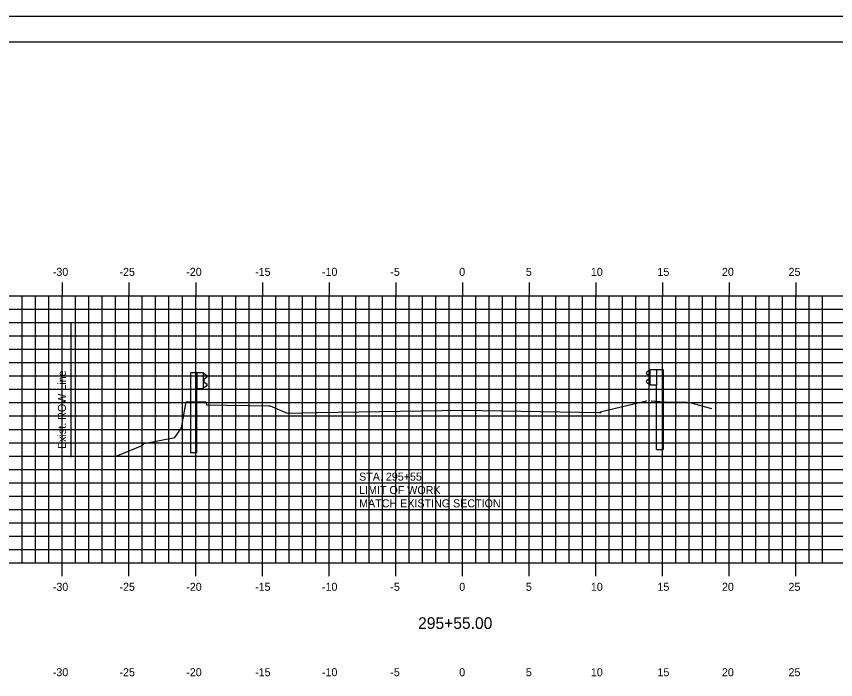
# Model space of a CAD drawing. Extents: x 859575 to 859745, y 366268 to 366378.
# Drawn here: x 859624.4 to 859685.8, y 366328.5 to 366378.2 of the extents above; entities that cross this region are included whole.
import ezdxf

# ---------------------------------------------------------------- set-up
doc = ezdxf.new("R2010")
doc.units = 0
for name, color, linetype in [('BORDER', 7, 'Continuous'), ('D_Text_Standard', 7, 'Continuous'), ('E_ROW_Line', 7, 'Continuous'), ('H_V ANNOTATION', 7, 'Continuous'), ('MAJOR', 7, 'Continuous'), ('MINOR', 7, 'Continuous'), ('PLOT BOUNDARY', 7, 'Continuous'), ('S_Guardrail_Beam', 7, 'Continuous'), ('S_Roadway_Centerline', 7, 'Continuous')]:
    doc.layers.add(name, color=color, linetype=linetype)

msp = doc.modelspace()

# ---------------------------------------------------------------- linework, layer by layer
at = {"layer": 'BORDER'}
msp.add_line((859742.797, 366376.236), (859582.797, 366376.236), dxfattribs=at)
at = {"layer": 'E_ROW_Line'}
msp.add_line((859628.47, 366345.162), (859628.47, 366355.162), dxfattribs=at)
at = {"layer": 'MAJOR'}
for p, q in [((859627.797, 366358.238), (859627.797, 366357.236)), ((859632.797, 366358.238), (859632.797, 366357.236)), ((859637.797, 366358.238), (859637.797, 366357.236)), ((859642.797, 366358.238), (859642.797, 366357.236)), ((859647.797, 366358.238), (859647.797, 366357.236)), ((859652.797, 366358.238), (859652.797, 366357.236)), ((859657.797, 366358.238), (859657.797, 366357.236)), ((859662.797, 366358.238), (859662.797, 366357.236)), ((859667.797, 366358.238), (859667.797, 366357.236)), ((859672.797, 366358.238), (859672.797, 366357.236)), ((859677.797, 366358.238), (859677.797, 366357.236)), ((859682.797, 366358.238), (859682.797, 366357.236)), ((859587.797, 366357.236), (859727.797, 366357.236)), ((859587.797, 366357.236), (859727.797, 366357.236)), ((859587.797, 366357.236), (859727.797, 366357.236)), ((859627.797, 366337.236), (859627.797, 366357.236)), ((859627.797, 366337.236), (859627.797, 366357.236)), ((859632.797, 366337.236), (859632.797, 366357.236)), ((859632.797, 366337.236), (859632.797, 366357.236)), ((859637.797, 366337.236), (859637.797, 366357.236)), ((859637.797, 366337.236), (859637.797, 366357.236)), ((859642.797, 366337.236), (859642.797, 366357.236)), ((859642.797, 366337.236), (859642.797, 366357.236)), ((859647.797, 366337.236), (859647.797, 366357.236)), ((859647.797, 366337.236), (859647.797, 366357.236)), ((859652.797, 366337.236), (859652.797, 366357.236)), ((859652.797, 366337.236), (859652.797, 366357.236)), ((859657.797, 366337.236), (859657.797, 366357.236)), ((859657.797, 366337.236), (859657.797, 366357.236)), ((859662.797, 366337.236), (859662.797, 366357.236)), ((859662.797, 366337.236), (859662.797, 366357.236)), ((859667.797, 366337.236), (859667.797, 366357.236)), ((859667.797, 366337.236), (859667.797, 366357.236)), ((859672.797, 366337.236), (859672.797, 366357.236)), ((859672.797, 366337.236), (859672.797, 366357.236)), ((859677.797, 366337.236), (859677.797, 366357.236)), ((859677.797, 366337.236), (859677.797, 366357.236)), ((859682.797, 366337.236), (859682.797, 366357.236)), ((859682.797, 366337.236), (859682.797, 366357.236)), ((859587.797, 366352.236), (859727.797, 366352.236)), ((859587.797, 366352.236), (859727.797, 366352.236)), ((859587.797, 366347.236), (859727.797, 366347.236)), ((859587.797, 366347.236), (859727.797, 366347.236)), ((859587.797, 366342.236), (859727.797, 366342.236)), ((859587.797, 366342.236), (859727.797, 366342.236)), ((859587.797, 366337.236), (859727.797, 366337.236)), ((859587.797, 366337.236), (859727.797, 366337.236)), ((859587.797, 366337.236), (859727.797, 366337.236)), ((859627.797, 366336.234), (859627.797, 366337.236)), ((859632.797, 366336.234), (859632.797, 366337.236)), ((859637.797, 366336.234), (859637.797, 366337.236)), ((859642.797, 366336.234), (859642.797, 366337.236)), ((859647.797, 366336.234), (859647.797, 366337.236)), ((859652.797, 366336.234), (859652.797, 366337.236)), ((859657.797, 366336.234), (859657.797, 366337.236)), ((859662.797, 366336.234), (859662.797, 366337.236)), ((859667.797, 366336.234), (859667.797, 366337.236)), ((859672.797, 366336.234), (859672.797, 366337.236)), ((859677.797, 366336.234), (859677.797, 366337.236)), ((859682.797, 366336.234), (859682.797, 366337.236))]:
    msp.add_line(p, q, dxfattribs=at)
at = {"layer": 'MINOR'}
for p, q in [((859624.797, 366337.236), (859624.797, 366357.236)), ((859624.797, 366337.236), (859624.797, 366357.236)), ((859625.797, 366337.236), (859625.797, 366357.236)), ((859625.797, 366337.236), (859625.797, 366357.236)), ((859626.797, 366337.236), (859626.797, 366357.236)), ((859626.797, 366337.236), (859626.797, 366357.236)), ((859628.797, 366337.236), (859628.797, 366357.236)), ((859628.797, 366337.236), (859628.797, 366357.236)), ((859629.797, 366337.236), (859629.797, 366357.236)), ((859629.797, 366337.236), (859629.797, 366357.236)), ((859630.797, 366337.236), (859630.797, 366357.236)), ((859630.797, 366337.236), (859630.797, 366357.236)), ((859631.797, 366337.236), (859631.797, 366357.236)), ((859631.797, 366337.236), (859631.797, 366357.236)), ((859633.797, 366337.236), (859633.797, 366357.236)), ((859633.797, 366337.236), (859633.797, 366357.236)), ((859634.797, 366337.236), (859634.797, 366357.236)), ((859634.797, 366337.236), (859634.797, 366357.236)), ((859635.797, 366337.236), (859635.797, 366357.236)), ((859635.797, 366337.236), (859635.797, 366357.236)), ((859636.797, 366337.236), (859636.797, 366357.236)), ((859636.797, 366337.236), (859636.797, 366357.236)), ((859638.797, 366337.236), (859638.797, 366357.236)), ((859638.797, 366337.236), (859638.797, 366357.236)), ((859639.797, 366337.236), (859639.797, 366357.236)), ((859639.797, 366337.236), (859639.797, 366357.236)), ((859640.797, 366337.236), (859640.797, 366357.236)), ((859640.797, 366337.236), (859640.797, 366357.236)), ((859641.797, 366337.236), (859641.797, 366357.236)), ((859641.797, 366337.236), (859641.797, 366357.236)), ((859643.797, 366337.236), (859643.797, 366357.236)), ((859643.797, 366337.236), (859643.797, 366357.236)), ((859644.797, 366337.236), (859644.797, 366357.236)), ((859644.797, 366337.236), (859644.797, 366357.236)), ((859645.797, 366337.236), (859645.797, 366357.236)), ((859645.797, 366337.236), (859645.797, 366357.236)), ((859646.797, 366337.236), (859646.797, 366357.236)), ((859646.797, 366337.236), (859646.797, 366357.236)), ((859648.797, 366337.236), (859648.797, 366357.236)), ((859648.797, 366337.236), (859648.797, 366357.236)), ((859649.797, 366337.236), (859649.797, 366357.236)), ((859649.797, 366337.236), (859649.797, 366357.236)), ((859650.797, 366337.236), (859650.797, 366357.236)), ((859650.797, 366337.236), (859650.797, 366357.236)), ((859651.797, 366337.236), (859651.797, 366357.236)), ((859651.797, 366337.236), (859651.797, 366357.236)), ((859653.797, 366337.236), (859653.797, 366357.236)), ((859653.797, 366337.236), (859653.797, 366357.236)), ((859654.797, 366337.236), (859654.797, 366357.236)), ((859654.797, 366337.236), (859654.797, 366357.236)), ((859655.797, 366337.236), (859655.797, 366357.236)), ((859655.797, 366337.236), (859655.797, 366357.236)), ((859656.797, 366337.236), (859656.797, 366357.236)), ((859656.797, 366337.236), (859656.797, 366357.236)), ((859658.797, 366337.236), (859658.797, 366357.236)), ((859658.797, 366337.236), (859658.797, 366357.236)), ((859659.797, 366337.236), (859659.797, 366357.236)), ((859659.797, 366337.236), (859659.797, 366357.236)), ((859660.797, 366337.236), (859660.797, 366357.236)), ((859660.797, 366337.236), (859660.797, 366357.236)), ((859661.797, 366337.236), (859661.797, 366357.236)), ((859661.797, 366337.236), (859661.797, 366357.236)), ((859663.797, 366337.236), (859663.797, 366357.236)), ((859663.797, 366337.236), (859663.797, 366357.236)), ((859664.797, 366337.236), (859664.797, 366357.236)), ((859664.797, 366337.236), (859664.797, 366357.236)), ((859665.797, 366337.236), (859665.797, 366357.236)), ((859665.797, 366337.236), (859665.797, 366357.236)), ((859666.797, 366337.236), (859666.797, 366357.236)), ((859666.797, 366337.236), (859666.797, 366357.236)), ((859668.797, 366337.236), (859668.797, 366357.236)), ((859668.797, 366337.236), (859668.797, 366357.236)), ((859669.797, 366337.236), (859669.797, 366357.236)), ((859669.797, 366337.236), (859669.797, 366357.236)), ((859670.797, 366337.236), (859670.797, 366357.236)), ((859670.797, 366337.236), (859670.797, 366357.236)), ((859671.797, 366337.236), (859671.797, 366357.236)), ((859671.797, 366337.236), (859671.797, 366357.236)), ((859673.797, 366337.236), (859673.797, 366357.236)), ((859673.797, 366337.236), (859673.797, 366357.236)), ((859674.797, 366337.236), (859674.797, 366357.236)), ((859674.797, 366337.236), (859674.797, 366357.236)), ((859675.797, 366337.236), (859675.797, 366357.236)), ((859675.797, 366337.236), (859675.797, 366357.236)), ((859676.797, 366337.236), (859676.797, 366357.236)), ((859676.797, 366337.236), (859676.797, 366357.236)), ((859678.797, 366337.236), (859678.797, 366357.236)), ((859678.797, 366337.236), (859678.797, 366357.236)), ((859679.797, 366337.236), (859679.797, 366357.236)), ((859679.797, 366337.236), (859679.797, 366357.236)), ((859680.797, 366337.236), (859680.797, 366357.236)), ((859680.797, 366337.236), (859680.797, 366357.236)), ((859681.797, 366337.236), (859681.797, 366357.236)), ((859681.797, 366337.236), (859681.797, 366357.236)), ((859683.797, 366337.236), (859683.797, 366357.236)), ((859683.797, 366337.236), (859683.797, 366357.236)), ((859684.797, 366337.236), (859684.797, 366357.236)), ((859684.797, 366337.236), (859684.797, 366357.236)), ((859587.797, 366356.236), (859727.797, 366356.236)), ((859587.797, 366356.236), (859727.797, 366356.236)), ((859587.797, 366355.236), (859727.797, 366355.236)), ((859587.797, 366355.236), (859727.797, 366355.236)), ((859587.797, 366354.236), (859727.797, 366354.236)), ((859587.797, 366354.236), (859727.797, 366354.236)), ((859587.797, 366353.236), (859727.797, 366353.236)), ((859587.797, 366353.236), (859727.797, 366353.236)), ((859587.797, 366351.236), (859727.797, 366351.236)), ((859587.797, 366351.236), (859727.797, 366351.236)), ((859587.797, 366350.236), (859727.797, 366350.236)), ((859587.797, 366350.236), (859727.797, 366350.236)), ((859587.797, 366349.236), (859727.797, 366349.236)), ((859587.797, 366349.236), (859727.797, 366349.236)), ((859587.797, 366348.236), (859727.797, 366348.236)), ((859587.797, 366348.236), (859727.797, 366348.236)), ((859587.797, 366346.236), (859727.797, 366346.236)), ((859587.797, 366346.236), (859727.797, 366346.236)), ((859587.797, 366345.236), (859727.797, 366345.236)), ((859587.797, 366345.236), (859727.797, 366345.236)), ((859587.797, 366344.236), (859727.797, 366344.236)), ((859587.797, 366344.236), (859727.797, 366344.236)), ((859587.797, 366343.236), (859727.797, 366343.236)), ((859587.797, 366343.236), (859727.797, 366343.236)), ((859587.797, 366341.236), (859727.797, 366341.236)), ((859587.797, 366341.236), (859727.797, 366341.236)), ((859587.797, 366340.236), (859727.797, 366340.236)), ((859587.797, 366340.236), (859727.797, 366340.236)), ((859587.797, 366339.236), (859727.797, 366339.236)), ((859587.797, 366339.236), (859727.797, 366339.236)), ((859587.797, 366338.236), (859727.797, 366338.236)), ((859587.797, 366338.236), (859727.797, 366338.236))]:
    msp.add_line(p, q, dxfattribs=at)
at = {"layer": 'PLOT BOUNDARY'}
msp.add_lwpolyline([(859574.704, 366268.177), (859744.704, 366268.177), (859744.704, 366378.177), (859574.704, 366378.177)], close=True, dxfattribs=at)
at = {"layer": 'S_Guardrail_Beam'}
for p, q in [((859637.404, 366351.472), (859637.404, 366345.472)), ((859637.895, 366351.472), (859637.404, 366351.472)), ((859638.385, 366351.472), (859637.895, 366351.472)), ((859637.895, 366351.472), (859637.895, 366350.306)), ((859638.385, 366350.306), (859638.385, 366351.472)), ((859638.385, 366351.4), (859638.467, 366351.385)), ((859638.484, 366351.378), (859638.627, 366351.278)), ((859671.76, 366351.63), (859671.616, 366351.53)), ((859671.616, 366351.387), (859671.812, 366351.25)), ((859671.859, 366351.651), (859671.776, 366351.636)), ((859671.859, 366351.724), (859672.348, 366351.724)), ((859671.859, 366350.557), (859671.859, 366351.724)), ((859672.348, 366351.724), (859672.84, 366351.724)), ((859672.348, 366351.724), (859672.348, 366350.557)), ((859672.84, 366351.724), (859672.84, 366345.724)), ((859638.398, 366350.935), (859638.398, 366350.844)), ((859638.627, 366351.135), (859638.432, 366350.999)), ((859638.432, 366350.779), (859638.627, 366350.643)), ((859671.812, 366351.031), (859671.616, 366350.894)), ((859671.616, 366350.751), (859671.76, 366350.651)), ((859671.776, 366350.644), (859671.859, 366350.63)), ((859671.845, 366351.186), (859671.845, 366351.095)), ((859637.895, 366345.472), (859637.895, 366350.306)), ((859637.895, 366350.306), (859638.385, 366350.306)), ((859638.467, 366350.393), (859638.385, 366350.379)), ((859638.627, 366350.5), (859638.484, 366350.4)), ((859672.348, 366350.557), (859671.859, 366350.557)), ((859672.348, 366345.724), (859672.348, 366350.557)), ((859672.348, 366345.724), (859672.84, 366345.724)), ((859637.895, 366345.472), (859637.404, 366345.472))]:
    msp.add_line(p, q, dxfattribs=at)
for centre, major_axis, start_param, end_param in [((859638.46, 366351.344), (0.0417, 0), 0.959931, 1.396263), ((859638.577, 366351.207), (0.0877, 0), 5.323254, 7.243116), ((859671.667, 366351.458), (-0.0877, 0), 5.323254, 7.243116), ((859671.784, 366351.596), (-0.0417, 0), 4.886922, 5.323254), ((859671.766, 366351.186), (0.0789, 0), 0, 0.959931), ((859638.477, 366350.935), (-0.0789, 0), 5.323254, 6.283185), ((859638.477, 366350.844), (-0.0789, 0), 6.283185, 7.243116), ((859638.577, 366350.572), (0.0877, 0), 5.323254, 7.243116), ((859671.667, 366350.823), (-0.0877, 0), 5.323254, 7.243116), ((859671.784, 366350.685), (-0.0417, 0), 0.959931, 1.396263), ((859671.766, 366351.095), (0.0789, 0), 5.323254, 6.283185), ((859638.46, 366350.434), (0.0417, 0), 4.886922, 5.323254)]:
    msp.add_ellipse(centre, major_axis=major_axis, ratio=0.995501, start_param=start_param, end_param=end_param, dxfattribs=at)
at = {"layer": 'S_Roadway_Centerline'}
for points in [[(859631.847, 366345.214), (859633.791, 366346.014), (859633.929, 366346.179), (859636.241, 366346.617), (859636.743, 366347.345), (859637.096, 366349.304), (859638.17, 366349.299), (859638.515, 366349.299), (859638.548, 366349.299), (859638.611, 366349.061), (859638.614, 366349.066), (859643.255, 366349.009), (859643.389, 366348.99), (859644.647, 366348.438), (859646.805, 366348.5), (859646.842, 366348.5), (859646.896, 366348.501), (859657.795, 366348.678), (859668.019, 366348.509), (859668.025, 366348.509), (859668.033, 366348.508), (859668.034, 366348.508), (859668.16, 366348.505), (859668.23, 366348.56), (859671.584, 366349.371), (859671.588, 366349.39)], [(859671.95, 366349.372), (859673.271, 366349.275), (859673.299, 366349.274), (859674.629, 366349.262), (859674.842, 366349.259), (859676.474, 366348.785)]]:
    msp.add_lwpolyline(points, dxfattribs=at)

# ---------------------------------------------------------------- texts
at = {"layer": 'D_Text_Standard'}
for s, p in [('STA. 295+55', (859650.05, 366343.392)), ('LIMIT OF WORK', (859650.05, 366342.392)), ('MATCH EXISTING SECTION', (859650.05, 366341.392))]:
    msp.add_text(s, height=0.6, dxfattribs=at).set_placement(p)
at = {"layer": 'E_ROW_Line'}
msp.add_text('Exist. ROW Line', height=0.6, rotation=90, dxfattribs=at).set_placement((859628.07, 366345.762))
at = {"layer": 'H_V ANNOTATION'}
for s, height, p in [('-30', 0.6, (859627.085, 366358.736)), ('-25', 0.6, (859632.083, 366358.736)), ('-20', 0.6, (859637.091, 366358.736)), ('-15', 0.6, (859642.254, 366358.736)), ('-10', 0.6, (859647.262, 366358.736)), ('-5', 0.6, (859652.388, 366358.736)), ('0', 0.6, (859657.556, 366358.736)), ('5', 0.6, (859662.548, 366358.736)), ('10', 0.6, (859667.423, 366358.736)), ('15', 0.6, (859672.415, 366358.736)), ('20', 0.6, (859677.251, 366358.736)), ('25', 0.6, (859682.243, 366358.736)), ('-30', 0.6, (859627.085, 366335.136)), ('-25', 0.6, (859632.083, 366335.136)), ('-20', 0.6, (859637.091, 366335.136)), ('-15', 0.6, (859642.254, 366335.136)), ('-10', 0.6, (859647.262, 366335.136)), ('-5', 0.6, (859652.388, 366335.136)), ('0', 0.6, (859657.556, 366335.136)), ('5', 0.6, (859662.548, 366335.136)), ('10', 0.6, (859667.423, 366335.136)), ('15', 0.6, (859672.415, 366335.136)), ('20', 0.6, (859677.251, 366335.136)), ('25', 0.6, (859682.243, 366335.136)), ('295+55.00', 0.875, (859654.473, 366332.28)), ('-30', 0.6, (859627.085, 366328.736)), ('-25', 0.6, (859632.083, 366328.736)), ('-20', 0.6, (859637.091, 366328.736)), ('-15', 0.6, (859642.254, 366328.736)), ('-10', 0.6, (859647.262, 366328.736)), ('-5', 0.6, (859652.388, 366328.736)), ('0', 0.6, (859657.556, 366328.736)), ('5', 0.6, (859662.548, 366328.736)), ('10', 0.6, (859667.423, 366328.736)), ('15', 0.6, (859672.415, 366328.736)), ('20', 0.6, (859677.251, 366328.736)), ('25', 0.6, (859682.243, 366328.736))]:
    msp.add_text(s, height=height, dxfattribs=at).set_placement(p)
at = {"layer": 'S_Roadway_Centerline'}
for s, p in [('L', (859657.787, 366348.671)), ('C', (859657.79, 366348.678))]:
    msp.add_text(s, height=0.0146, dxfattribs=at).set_placement(p)

doc.saveas('drawing.dxf')
